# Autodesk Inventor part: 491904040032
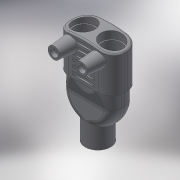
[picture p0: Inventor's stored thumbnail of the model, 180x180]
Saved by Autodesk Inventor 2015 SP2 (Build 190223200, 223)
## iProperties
Created: 2017-07
Part Number: 491904040032
Material: Generic
Description: PLASSON REDUCING Y 40X32X32
Document SubType Name: Modeling
Designer: KIM
Density: 1 g/cm^3
Appearance: Default
Author: KIM
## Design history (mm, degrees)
derived "491904.ipt"
feature "Solid1::491904.ipt"
tag "TaggingFeature1"
body "Solid1"
other parameters: "d0" = 87, "d1" = 108, "d2" = 21.6, "d3" = 8.7, "d4" = 86.4, "d5" = 52.2, "d6" = 45, "d7" = 0, "d8" = 32.4, "d9" = 32.4, "d10" = 20.25, "d11" = 2.25, "d12" = -21.6, "d13" = 20.25, "d14" = 34.8, "d15" = 54, "d16" = 0, "d17" = -4.32, "d18" = 4.32, "d19" = 0, "d22" = 8.1, "d32" = 32, "d33" = 32, "d34" = 43.5, "d35" = 21.75, "d36" = 43, "d37" = 0, "d38" = 35.2, "d39" = 35.2, "d40" = 10.75, "d41" = 0, "d42" = 28.8, "d43" = 180 deg, "d52" = 108, "d53" = 102.6, "d54" = 54, "d55" = 78.3, "d56" = 39.15, "d57" = 26.1, "d58" = 133, "d60" = 32, "d62" = 18, "d64" = 0, "d66" = 0.4, "d71" = 12.96, "d72" = 1.33, "d73" = 8.8, "d75" = 64.8, "d76" = 0, "d77" = 8, "d78" = 42, "d79" = 15, "d80" = 15, "d81" = 23.4, "d82" = 5 deg, "d83" = 4, "d84" = 4, "d87" = 14, "d88" = 0, "d89" = 3.99, "d90" = 3, "d91" = 0, "d_1" = 32, "L_" = 45, "L_1" = 43, "H_1" = 108, "B_" = 87, "d_2" = 12, "H_" = 133, "A_" = 42
